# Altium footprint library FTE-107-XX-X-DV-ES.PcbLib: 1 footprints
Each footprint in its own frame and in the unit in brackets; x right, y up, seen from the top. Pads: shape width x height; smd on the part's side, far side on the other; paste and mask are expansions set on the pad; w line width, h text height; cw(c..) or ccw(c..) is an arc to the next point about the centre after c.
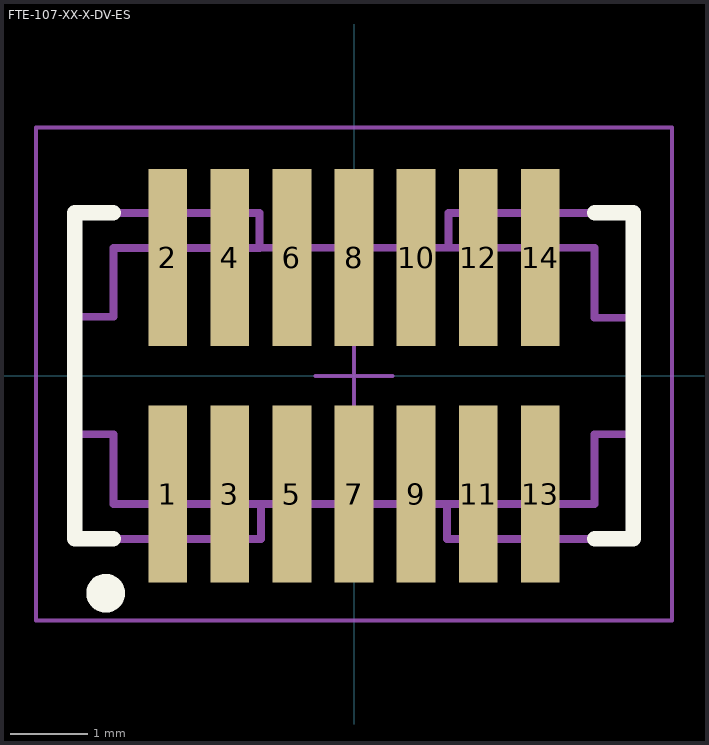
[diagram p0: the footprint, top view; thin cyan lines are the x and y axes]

## FTE-107-XX-X-DV-ES [mm] "0.80mm pitch, 14 pin, terminal strip assembly; low profile"
height 4.09
pads (14):
  rect 0.5x2.28 smd mask+0: 1(-2.4,-1.524) 2(-2.4,1.524) 3(-1.6,-1.524) 4(-1.6,1.524) 5(-0.8,-1.524) 6(-0.8,1.524) 7(0,-1.524) 8(0,1.524) 9(0.8,-1.524) 10(0.8,1.524) 11(1.6,-1.524) 12(1.6,1.524) 13(2.4,-1.524) 14(2.4,1.524)
Top Overlay:
  circle w0.25: c-3.2,-2.8 r0.125
  lines w0.2: -3.1,-2.1 -3.6,-2.1 -3.6,2.1 -3.1,2.1 ; 3.1,-2.1 3.6,-2.1 3.6,2.1 3.1,2.1
Mechanical 12:
  lines w0.001: -3.6,-2.1 -1.2,-2.1 -1.2,-1.65 1.2,-1.65 1.2,-2.1 3.6,-2.1 3.6,2.1 1.219,2.1 1.219,1.651 -1.219,1.651 -1.219,2.1 -3.6,2.1 -3.6,-2.1
Mechanical 13:
  lines w0.1: -3.6,-0.75 -3.1,-0.75 -3.1,-1.65 -1.2,-1.65 ; -3.6,0.762 -3.1,0.762 -3.1,1.65 -1.219,1.65 ; 3.6,-0.75 3.1,-0.75 3.1,-1.65 1.2,-1.65 ; 3.6,0.75 3.1,0.75 3.1,1.651 1.219,1.651 ; -1.2,-1.65 1.2,-1.65 ; -1.2,-1.65 -1.2,-2.1 -3.6,-2.1 -3.6,2.1 -1.219,2.1 -1.219,1.651 1.219,1.651 ; 1.2,-1.65 1.2,-2.1 3.6,-2.1 3.6,2.1 1.219,2.1 1.219,1.651
  text ".Designator" at 0.254,0.254 h1.52
Mechanical 15:
  lines w0.05: -0.5,0 0.5,0 ; 0,-0.5 0,0.5 ; -4.1,-3.15 4.1,-3.15 4.1,3.2 -4.1,3.2 -4.1,-3.15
